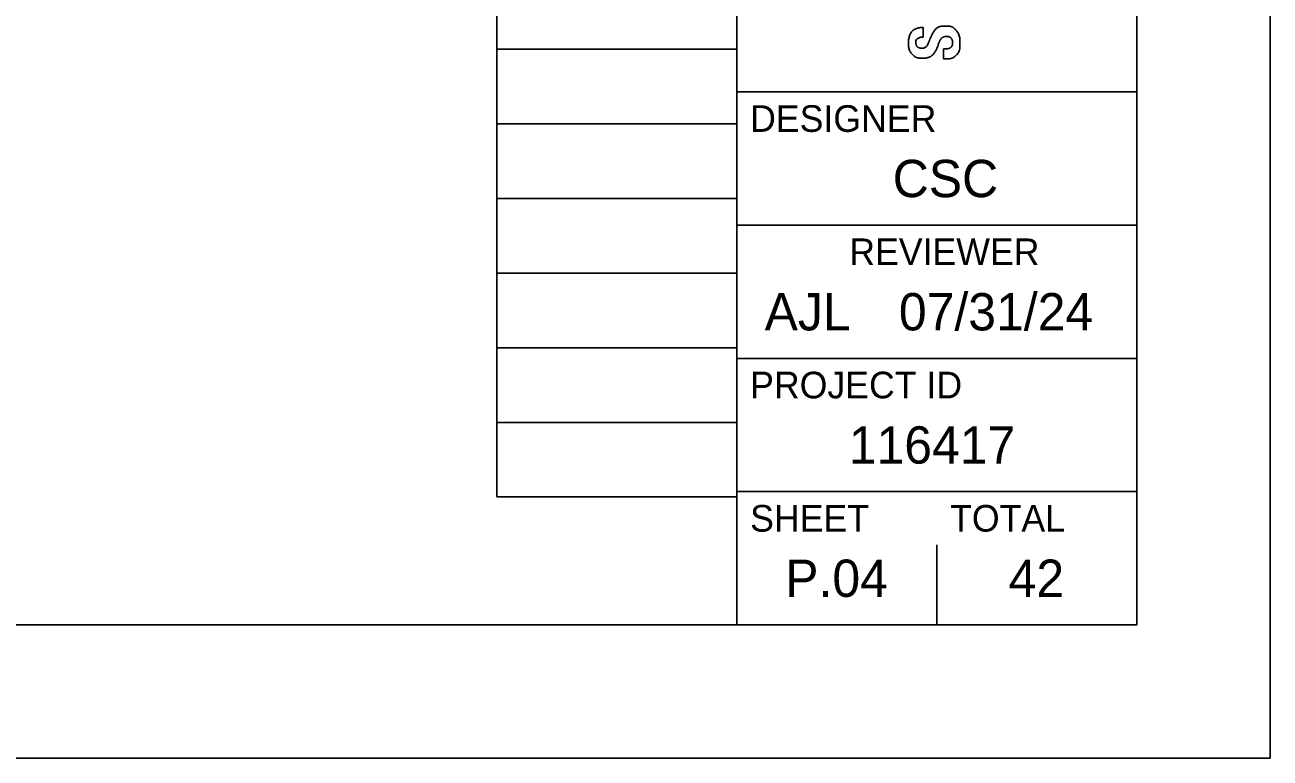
# Model space of a CAD drawing. Extents: x 0 to 84.3, y -13.4 to 22.
# Drawn here: x 29.33 to 34, y 0 to 2.751 of the extents above; entities that cross this region are included whole.
import ezdxf

# ---------------------------------------------------------------- set-up
doc = ezdxf.new("R2010")
doc.units = 0
for name, color, linetype in [('SH_Border', 7, 'Continuous'), ('SH_Cut_Line', 7, 'Continuous'), ('SH_Data', 7, 'Continuous')]:
    doc.layers.add(name, color=color, linetype=linetype)

msp = doc.modelspace()

# ---------------------------------------------------------------- linework, layer by layer
at = {"layer": 'SH_Border'}
for p, q in [((32, 0.5), (32, 21.5)), ((32, 2.5), (33.5, 2.5)), ((32, 2), (33.5, 2)), ((32, 1.5), (33.5, 1.5)), ((32, 1), (33.5, 1))]:
    msp.add_line(p, q, dxfattribs=at)
msp.add_lwpolyline([(1.5, 21.5), (33.5, 21.5), (33.5, 0.5), (1.5, 0.5)], close=True, dxfattribs=at)
at = {"layer": 'SH_Cut_Line'}
msp.add_lwpolyline([(0, 0), (34, 0), (34, 22), (0, 22)], close=True, dxfattribs=at)
at = {"layer": 'SH_Data'}
for p, q in [((31.1, 0.98), (31.1, 21.14)), ((32, 0.98), (32, 21.14)), ((31.1, 2.66), (32, 2.66)), ((31.1, 2.38), (32, 2.38)), ((31.1, 2.1), (32, 2.1)), ((31.1, 1.82), (32, 1.82)), ((31.1, 1.54), (32, 1.54)), ((31.1, 1.26), (32, 1.26)), ((31.1, 0.98), (32, 0.98)), ((32.75, 0.5), (32.75, 0.8)), ((32.375, 0.675), (32.375, 0.675))]:
    msp.add_line(p, q, dxfattribs=at)
msp.add_open_spline([(32.7753, 2.6613), (32.7753, 2.6613), (32.7807, 2.6613), (32.7807, 2.6613), (32.785, 2.6613), (32.789, 2.6616), (32.7925, 2.6623), (32.7961, 2.663), (32.7991, 2.6643), (32.8015, 2.6662), (32.8039, 2.6681), (32.8058, 2.6706), (32.8072, 2.6737), (32.8086, 2.6769), (32.8093, 2.6809), (32.8093, 2.6859), (32.8093, 2.6916), (32.8074, 2.6968), (32.8037, 2.7014), (32.8, 2.7059), (32.7942, 2.7082), (32.7864, 2.7082), (32.7822, 2.7082), (32.7787, 2.7077), (32.7756, 2.7066), (32.7726, 2.7054), (32.7699, 2.7036), (32.7674, 2.701), (32.765, 2.6984), (32.7628, 2.695), (32.7608, 2.6907), (32.7588, 2.6865), (32.7568, 2.6813), (32.7547, 2.6751), (32.7519, 2.6667), (32.7489, 2.6596), (32.7455, 2.6535), (32.7421, 2.6475), (32.7382, 2.6424), (32.7339, 2.6384), (32.7296, 2.6343), (32.7246, 2.6313), (32.7188, 2.6294), (32.7131, 2.6275), (32.7064, 2.6266), (32.6986, 2.6266), (32.6804, 2.6266), (32.6667, 2.6316), (32.6576, 2.6418), (32.6485, 2.652), (32.644, 2.666), (32.644, 2.6838), (32.644, 2.6921), (32.6449, 2.6997), (32.6467, 2.7067), (32.6485, 2.7137), (32.6515, 2.7198), (32.6555, 2.7249), (32.6596, 2.73), (32.6648, 2.7339), (32.6711, 2.7368), (32.6774, 2.7396), (32.685, 2.7411), (32.6938, 2.7411), (32.6938, 2.7411), (32.699, 2.7411), (32.699, 2.7411), (32.699, 2.7411), (32.699, 2.7052), (32.699, 2.7052), (32.6902, 2.7052), (32.6834, 2.7036), (32.6786, 2.7005), (32.6739, 2.6975), (32.6715, 2.6923), (32.6715, 2.6851), (32.6715, 2.681), (32.6721, 2.6775), (32.6733, 2.6748), (32.6745, 2.672), (32.6761, 2.6698), (32.6781, 2.6682), (32.6801, 2.6666), (32.6824, 2.6655), (32.685, 2.6649), (32.6876, 2.6643), (32.6903, 2.664), (32.6931, 2.664), (32.6988, 2.664), (32.7036, 2.6652), (32.7075, 2.6676), (32.7114, 2.67), (32.715, 2.6752), (32.7183, 2.6831), (32.7183, 2.6831), (32.7307, 2.7119), (32.7307, 2.7119), (32.7338, 2.7188), (32.7371, 2.7246), (32.7405, 2.7292), (32.7438, 2.7337), (32.7475, 2.7374), (32.7514, 2.74), (32.7553, 2.7427), (32.7596, 2.7446), (32.7643, 2.7456), (32.7689, 2.7467), (32.7741, 2.7472), (32.7798, 2.7472), (32.7994, 2.7472), (32.8138, 2.7415), (32.823, 2.7302), (32.8322, 2.7188), (32.8367, 2.703), (32.8367, 2.6828), (32.8367, 2.6617), (32.832, 2.6466), (32.8226, 2.6375), (32.8132, 2.6284), (32.7999, 2.6239), (32.7828, 2.6239), (32.7828, 2.6239), (32.7753, 2.6239), (32.7753, 2.6239), (32.7753, 2.6239), (32.7753, 2.6613), (32.7753, 2.6613)], degree=3, dxfattribs=at)

# ---------------------------------------------------------------- texts
for s, height, p in [('DESIGNER', 0.1, (32.05, 2.35)), ('CSC', 0.14, (32.5847, 2.105)), ('REVIEWER', 0.1, (32.4218, 1.85)), ('AJL', 0.14, (32.1043, 1.605)), ('07/31/24', 0.14, (32.6078, 1.605)), ('PROJECT ID', 0.1, (32.05, 1.35)), ('116417', 0.14, (32.4198, 1.105)), ('SHEET', 0.1, (32.05, 0.85)), ('TOTAL', 0.1, (32.8, 0.85)), ('P.04', 0.14, (32.1816, 0.605)), ('42', 0.14, (33.0194, 0.605))]:
    msp.add_text(s, height=height, dxfattribs=at).set_placement(p)

doc.saveas('drawing.dxf')
